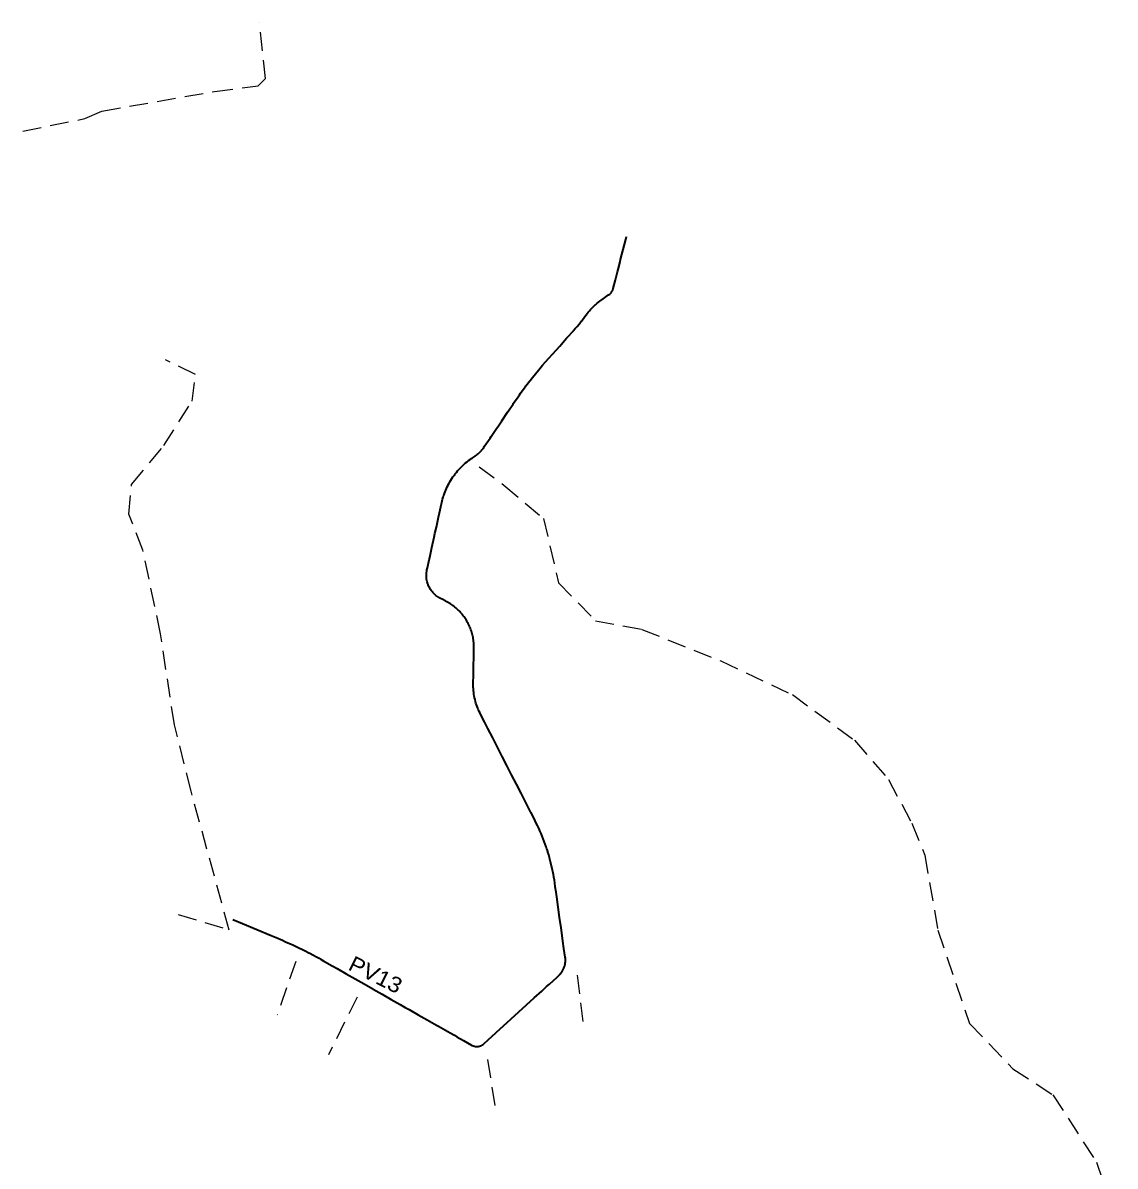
# Model space of a CAD drawing. Extents: x -509392 to -507242, y -1124532 to -1120864.
# Drawn here: x -508322 to -507268, y -1121966 to -1120864 of the extents above; entities that cross this region are included whole.
import ezdxf
from ezdxf.enums import TextEntityAlignment as Align

# ---------------------------------------------------------------- set-up
doc = ezdxf.new("R2010")
doc.units = 0
doc.header["$LTSCALE"] = 6
doc.linetypes.add('DOT_DASHED', pattern=[7.7, 5, -1.2, 0.3, -1.2])
doc.linetypes.add('MEDIUM_DASHED', pattern=[4.5, 3, -1.5])
for name, color, linetype, lineweight in [('1', 7, 'DOT_DASHED', 25), ('15', 7, 'Continuous', 35), ('3', 7, 'MEDIUM_DASHED', 25)]:
    doc.layers.add(name, color=color, linetype=linetype, lineweight=lineweight)

msp = doc.modelspace()

# ---------------------------------------------------------------- linework, layer by layer
at = {"layer": '15'}
for points in [[(-507782.882, -1121151.137), (-507781.865, -1121149.831), (-507780.179, -1121147.611), (-507778.672, -1121145.57), (-507778.55, -1121145.402), (-507778.444, -1121145.254), (-507777.436, -1121143.907), (-507776.359, -1121142.55), (-507775.242, -1121141.225), (-507774.089, -1121139.933), (-507772.897, -1121138.674), (-507771.689, -1121137.468), (-507770.854, -1121136.674), (-507770.378, -1121136.235), (-507769.34, -1121135.309), (-507769.064, -1121135.069), (-507767.785, -1121133.998), (-507766.426, -1121132.924), (-507765.091, -1121131.931), (-507762.007, -1121129.704), (-507756.928, -1121126.038), (-507756.197, -1121125.51), (-507755.707, -1121125.139), (-507755.384, -1121124.868), (-507755.056, -1121124.569), (-507754.711, -1121124.221), (-507754.397, -1121123.877), (-507754.105, -1121123.522), (-507753.825, -1121123.149), (-507753.565, -1121122.767), (-507753.321, -1121122.37), (-507753.095, -1121121.961), (-507752.891, -1121121.548), (-507752.706, -1121121.125), (-507752.528, -1121120.659), (-507752.418, -1121120.334), (-507752.416, -1121120.326), (-507752.238, -1121119.691), (-507750.094, -1121111.277), (-507748.192, -1121103.816), (-507747.624, -1121101.587), (-507745.725, -1121094.135), (-507745.154, -1121091.896), (-507742.685, -1121082.206), (-507740.214, -1121072.515), (-507739.451, -1121069.522)], [(-507897.334, -1121290.467), (-507897.283, -1121290.42), (-507896.031, -1121289.267), (-507895.301, -1121288.621), (-507894.603, -1121288.022), (-507893.234, -1121286.888), (-507891.802, -1121285.763), (-507890.34, -1121284.676), (-507888.908, -1121283.667), (-507888.342, -1121283.279), (-507885.462, -1121281.307), (-507885.188, -1121281.119), (-507884.28, -1121280.474), (-507883.465, -1121279.852), (-507882.67, -1121279.201), (-507881.853, -1121278.485), (-507881.712, -1121278.355), (-507881.585, -1121278.236), (-507881.178, -1121277.848), (-507880.428, -1121277.093), (-507879.728, -1121276.338), (-507879.023, -1121275.524), (-507878.875, -1121275.345), (-507878.43, -1121274.789), (-507877.798, -1121273.949), (-507877.158, -1121273.035), (-507876.624, -1121272.245), (-507871.03, -1121263.958), (-507869.988, -1121262.415), (-507865.434, -1121255.67), (-507863.045, -1121252.133), (-507859.839, -1121247.384), (-507854.243, -1121239.096), (-507848.933, -1121231.231), (-507848.634, -1121230.787), (-507846.511, -1121227.683), (-507844.065, -1121224.181), (-507842.788, -1121222.382), (-507841.559, -1121220.671), (-507839.041, -1121217.22), (-507836.742, -1121214.136), (-507836.463, -1121213.765), (-507833.876, -1121210.372), (-507831.251, -1121207.002), (-507830.454, -1121205.995), (-507828.567, -1121203.63), (-507825.87, -1121200.314), (-507824.002, -1121198.058), (-507823.114, -1121196.997), (-507820.351, -1121193.741), (-507817.561, -1121190.522), (-507817.321, -1121190.248), (-507814.718, -1121187.309), (-507810.616, -1121182.725), (-507803.948, -1121175.272), (-507797.282, -1121167.819), (-507796.706, -1121167.175), (-507790.71, -1121160.473), (-507790.644, -1121160.399), (-507788.875, -1121158.391), (-507787.073, -1121156.286), (-507785.291, -1121154.142), (-507784.47, -1121153.131), (-507783.561, -1121151.998), (-507782.841, -1121151.085)], [(-507921.202, -1121417.324), (-507921.52, -1121417.114), (-507922.257, -1121416.595), (-507923.265, -1121415.818), (-507924.261, -1121414.961), (-507925.211, -1121414.055), (-507926.112, -1121413.098), (-507926.96, -1121412.099), (-507927.759, -1121411.051), (-507928.502, -1121409.961), (-507929.182, -1121408.84), (-507929.804, -1121407.683), (-507930.351, -1121406.523), (-507930.718, -1121405.639), (-507930.891, -1121405.195), (-507931.299, -1121404.024), (-507931.373, -1121403.763), (-507931.661, -1121402.775), (-507931.96, -1121401.499), (-507932.193, -1121400.204), (-507932.357, -1121398.895), (-507932.452, -1121397.587), (-507932.479, -1121396.279), (-507932.437, -1121394.964), (-507932.325, -1121393.652), (-507932.144, -1121392.346), (-507931.919, -1121391.184), (-507931.44, -1121389.003), (-507929.745, -1121381.293), (-507929.292, -1121379.234), (-507927.144, -1121369.468), (-507924.996, -1121359.703), (-507924.221, -1121356.177), (-507922.849, -1121349.936), (-507920.701, -1121340.17), (-507919.809, -1121336.112), (-507918.553, -1121330.402), (-507918.443, -1121329.902), (-507917.647, -1121326.281), (-507917.248, -1121324.573), (-507916.788, -1121322.814), (-507916.287, -1121321.081), (-507915.885, -1121319.801), (-507915.718, -1121319.291), (-507915.137, -1121317.612), (-507914.497, -1121315.909), (-507913.813, -1121314.223), (-507913.085, -1121312.557), (-507912.316, -1121310.91), (-507911.524, -1121309.324), (-507911.343, -1121308.977), (-507910.641, -1121307.665), (-507909.75, -1121306.093), (-507908.814, -1121304.534), (-507907.835, -1121302.998), (-507906.817, -1121301.488), (-507905.775, -1121300.027), (-507905.141, -1121299.176), (-507904.642, -1121298.524), (-507903.536, -1121297.132), (-507902.368, -1121295.737), (-507901.164, -1121294.372), (-507899.922, -1121293.037), (-507898.648, -1121291.739), (-507897.454, -1121290.582)], [(-507887.28, -1121504.061), (-507887.315, -1121502.529), (-507887.315, -1121502.349), (-507887.307, -1121500.793), (-507887.129, -1121492.21), (-507887.099, -1121490.723), (-507886.924, -1121482.21), (-507886.816, -1121477.005), (-507886.718, -1121472.214), (-507886.609, -1121466.872), (-507886.598, -1121465.504), (-507886.622, -1121464.203), (-507886.677, -1121462.95), (-507886.772, -1121461.61), (-507886.897, -1121460.314), (-507887.055, -1121459.025), (-507887.247, -1121457.741), (-507887.473, -1121456.46), (-507887.74, -1121455.147), (-507887.827, -1121454.757), (-507888.019, -1121453.939), (-507888.349, -1121452.66), (-507888.706, -1121451.41), (-507889.097, -1121450.167), (-507889.518, -1121448.939), (-507889.978, -1121447.704), (-507890.35, -1121446.769), (-507890.436, -1121446.562), (-507890.973, -1121445.321), (-507891.522, -1121444.14), (-507892.099, -1121442.976), (-507892.707, -1121441.828), (-507893.345, -1121440.693), (-507894.04, -1121439.53), (-507894.104, -1121439.426), (-507894.7, -1121438.49), (-507895.432, -1121437.398), (-507896.184, -1121436.336), (-507896.96, -1121435.299), (-507897.768, -1121434.278), (-507898.618, -1121433.257), (-507899.097, -1121432.705), (-507899.433, -1121432.329), (-507900.342, -1121431.346), (-507901.25, -1121430.416), (-507902.182, -1121429.507), (-507903.136, -1121428.625), (-507904.112, -1121427.769), (-507905.106, -1121426.942), (-507906.133, -1121426.13), (-507907.174, -1121425.353), (-507908.235, -1121424.601), (-507909.317, -1121423.877), (-507910.432, -1121423.17), (-507911.153, -1121422.736), (-507911.531, -1121422.515), (-507911.968, -1121422.265), (-507912.643, -1121421.89), (-507913.871, -1121421.241), (-507917.273, -1121419.5), (-507918.987, -1121418.623), (-507920.021, -1121418.058), (-507920.91, -1121417.511)], [(-507808.141, -1121696.703), (-507808.653, -1121693.059), (-507809.061, -1121690.295), (-507809.508, -1121687.553), (-507809.576, -1121687.156), (-507809.986, -1121684.866), (-507810.508, -1121682.153), (-507811.072, -1121679.439), (-507811.432, -1121677.802), (-507811.663, -1121676.787), (-507812.307, -1121674.081), (-507812.986, -1121671.409), (-507813.714, -1121668.702), (-507813.738, -1121668.616), (-507814.456, -1121666.098), (-507815.259, -1121663.426), (-507815.488, -1121662.686), (-507816.084, -1121660.818), (-507816.513, -1121659.51), (-507816.945, -1121658.23), (-507817.86, -1121655.606), (-507818.805, -1121653.014), (-507819.749, -1121650.538), (-507819.775, -1121650.469), (-507820.807, -1121647.88), (-507821.865, -1121645.332), (-507822.967, -1121642.782), (-507823.396, -1121641.816), (-507824.083, -1121640.3), (-507825.255, -1121637.79), (-507826.461, -1121635.304), (-507827.508, -1121633.216), (-507827.699, -1121632.841), (-507831.802, -1121624.83), (-507832.046, -1121624.352), (-507836.6, -1121615.46), (-507837.286, -1121614.122), (-507841.16, -1121606.556), (-507845.718, -1121597.655), (-507850.276, -1121588.754), (-507854.834, -1121579.854), (-507859.392, -1121570.953), (-507863.95, -1121562.052), (-507868.508, -1121553.151), (-507873.066, -1121544.252), (-507876.164, -1121538.203), (-507877.625, -1121535.351), (-507880.756, -1121529.236), (-507881.495, -1121527.739), (-507882.198, -1121526.205), (-507882.382, -1121525.784), (-507882.906, -1121524.537), (-507883.534, -1121522.926), (-507884.119, -1121521.285), (-507884.656, -1121519.627), (-507885.146, -1121517.955), (-507885.587, -1121516.267), (-507885.968, -1121514.612), (-507886.026, -1121514.334), (-507886.32, -1121512.855), (-507886.612, -1121511.141), (-507886.853, -1121509.413), (-507887.045, -1121507.681), (-507887.185, -1121505.944), (-507887.269, -1121504.351)], [(-507881.465, -1121850.53), (-507881.351, -1121850.501), (-507880.986, -1121850.398), (-507880.533, -1121850.252), (-507880.11, -1121850.094), (-507879.702, -1121849.92), (-507879.3, -1121849.727), (-507878.856, -1121849.49), (-507878.527, -1121849.292), (-507878.143, -1121849.039), (-507877.779, -1121848.776), (-507877.423, -1121848.493), (-507877, -1121848.125), (-507872.931, -1121844.415), (-507865.538, -1121837.678), (-507864.889, -1121837.087), (-507858.148, -1121830.944), (-507850.757, -1121824.208), (-507843.366, -1121817.472), (-507835.975, -1121810.736), (-507828.584, -1121804), (-507821.193, -1121797.264), (-507816.544, -1121793.027), (-507813.802, -1121790.528), (-507806.412, -1121783.795), (-507804.974, -1121782.483), (-507804.361, -1121781.903), (-507803.839, -1121781.371), (-507803.336, -1121780.818), (-507802.854, -1121780.247), (-507802.395, -1121779.66), (-507801.955, -1121779.052), (-507801.514, -1121778.393), (-507801.155, -1121777.806), (-507800.782, -1121777.145), (-507800.439, -1121776.482), (-507800.122, -1121775.806), (-507799.828, -1121775.116), (-507799.562, -1121774.421), (-507799.322, -1121773.713), (-507799.108, -1121772.996), (-507798.918, -1121772.258), (-507798.763, -1121771.548), (-507798.629, -1121770.806), (-507798.525, -1121770.072), (-507798.449, -1121769.328), (-507798.399, -1121768.58), (-507798.378, -1121767.835), (-507798.384, -1121767.085), (-507798.419, -1121766.335), (-507798.478, -1121765.624), (-507798.582, -1121764.761), (-507799.796, -1121756.119), (-507800.759, -1121749.259), (-507801.187, -1121746.217), (-507802.578, -1121736.313), (-507803.968, -1121726.41), (-507805.359, -1121716.508), (-507806.75, -1121706.605), (-507807.406, -1121701.936), (-507808.141, -1121696.702)], [(-508118.97, -1121728.348), (-508109.746, -1121732.211), (-508082.074, -1121743.8), (-508075.744, -1121746.451), (-508072.795, -1121747.699), (-508071.932, -1121748.07), (-508068.157, -1121749.718), (-508064.395, -1121751.406), (-508063.398, -1121751.861), (-508060.612, -1121753.151), (-508056.884, -1121754.916), (-508054.16, -1121756.234), (-508053.137, -1121756.735), (-508049.445, -1121758.575), (-508045.776, -1121760.449), (-508044.981, -1121760.862), (-508042.087, -1121762.382), (-508038.45, -1121764.334), (-508035.97, -1121765.692), (-508034.801, -1121766.339), (-508031.228, -1121768.351), (-508027.139, -1121770.681), (-508026.728, -1121770.915), (-508018.449, -1121775.63), (-508009.759, -1121780.58), (-508001.071, -1121785.53), (-507992.382, -1121790.479), (-507984.109, -1121795.192), (-507983.697, -1121795.426), (-507975.003, -1121800.379), (-507966.314, -1121805.328), (-507957.625, -1121810.278), (-507952.816, -1121813.017), (-507948.936, -1121815.228), (-507940.247, -1121820.177), (-507931.557, -1121825.127), (-507922.87, -1121830.077), (-507920.727, -1121831.297), (-507914.18, -1121835.026), (-507909.594, -1121837.638), (-507905.489, -1121839.976), (-507903.107, -1121841.333), (-507896.801, -1121844.926), (-507888.852, -1121849.454), (-507888.419, -1121849.69), (-507887.971, -1121849.906), (-507887.559, -1121850.084), (-507887.141, -1121850.241), (-507886.712, -1121850.381), (-507886.277, -1121850.502), (-507885.842, -1121850.602), (-507885.404, -1121850.682), (-507884.955, -1121850.744), (-507884.508, -1121850.785), (-507884.056, -1121850.806), (-507883.633, -1121850.807), (-507883.165, -1121850.786), (-507882.717, -1121850.747), (-507882.272, -1121850.687), (-507881.829, -1121850.608), (-507881.172, -1121850.459)]]:
    msp.add_lwpolyline(points, dxfattribs=at)
at = {"layer": '3'}
for p, q in [((-507881.569, -1121291.871), (-507857.682, -1121309.333)), ((-508171.775, -1121723.436), (-508121.704, -1121738.6)), ((-508058.415, -1121768.768), (-508076.33, -1121820.234)), ((-507787.067, -1121781.968), (-507781.555, -1121826.541)), ((-507999.295, -1121803.106), (-508026.857, -1121858.707)), ((-507873.428, -1121863.303), (-507866.079, -1121910.633))]:
    msp.add_line(p, q, dxfattribs=at)
for points in [[(-508321.551, -1120967.903), (-508261.833, -1120955.956), (-508245.296, -1120948.603), (-508136.885, -1120929.763), (-508094.623, -1120924.249), (-508087.732, -1120917.356), (-508093.245, -1120863.593)], [(-508122.623, -1121738.6), (-508159.372, -1121604.421), (-508175.45, -1121540.548), (-508188.772, -1121452.78), (-508205.72, -1121372.229), (-508219.501, -1121337.306), (-508216.745, -1121308.816), (-508185.508, -1121271.135), (-508158.405, -1121228.4), (-508155.189, -1121202.667), (-508184.13, -1121188.422)], [(-507857.682, -1121309.333), (-507819.564, -1121341.531), (-507805.132, -1121403.743), (-507769.431, -1121440.159), (-507724.615, -1121448.505), (-507648.655, -1121478.852), (-507579.532, -1121511.475), (-507519.524, -1121555.478), (-507486.861, -1121593.412), (-507464.469, -1121635.405), (-507451.893, -1121666.112), (-507439.256, -1121738.677), (-507408.669, -1121828.457), (-507367.095, -1121872.205), (-507328.355, -1121897.241), (-507286.361, -1121962.404), (-507268.347, -1122015.595)]]:
    msp.add_lwpolyline(points, dxfattribs=at)

# ---------------------------------------------------------------- texts
at = {"layer": '1', "width": 1.1}
msp.add_text('PV13', height=15, rotation=333.428, dxfattribs=at).set_placement((-507984.765, -1121788.259), align=Align.CENTER)

doc.saveas('drawing.dxf')
